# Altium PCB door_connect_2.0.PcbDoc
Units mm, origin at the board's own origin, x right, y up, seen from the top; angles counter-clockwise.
Board outline 40 x 48 mm, 2 copper layers (Top Layer, Bottom Layer); 2 components, 8 nets, 36 pads, 0 vias.
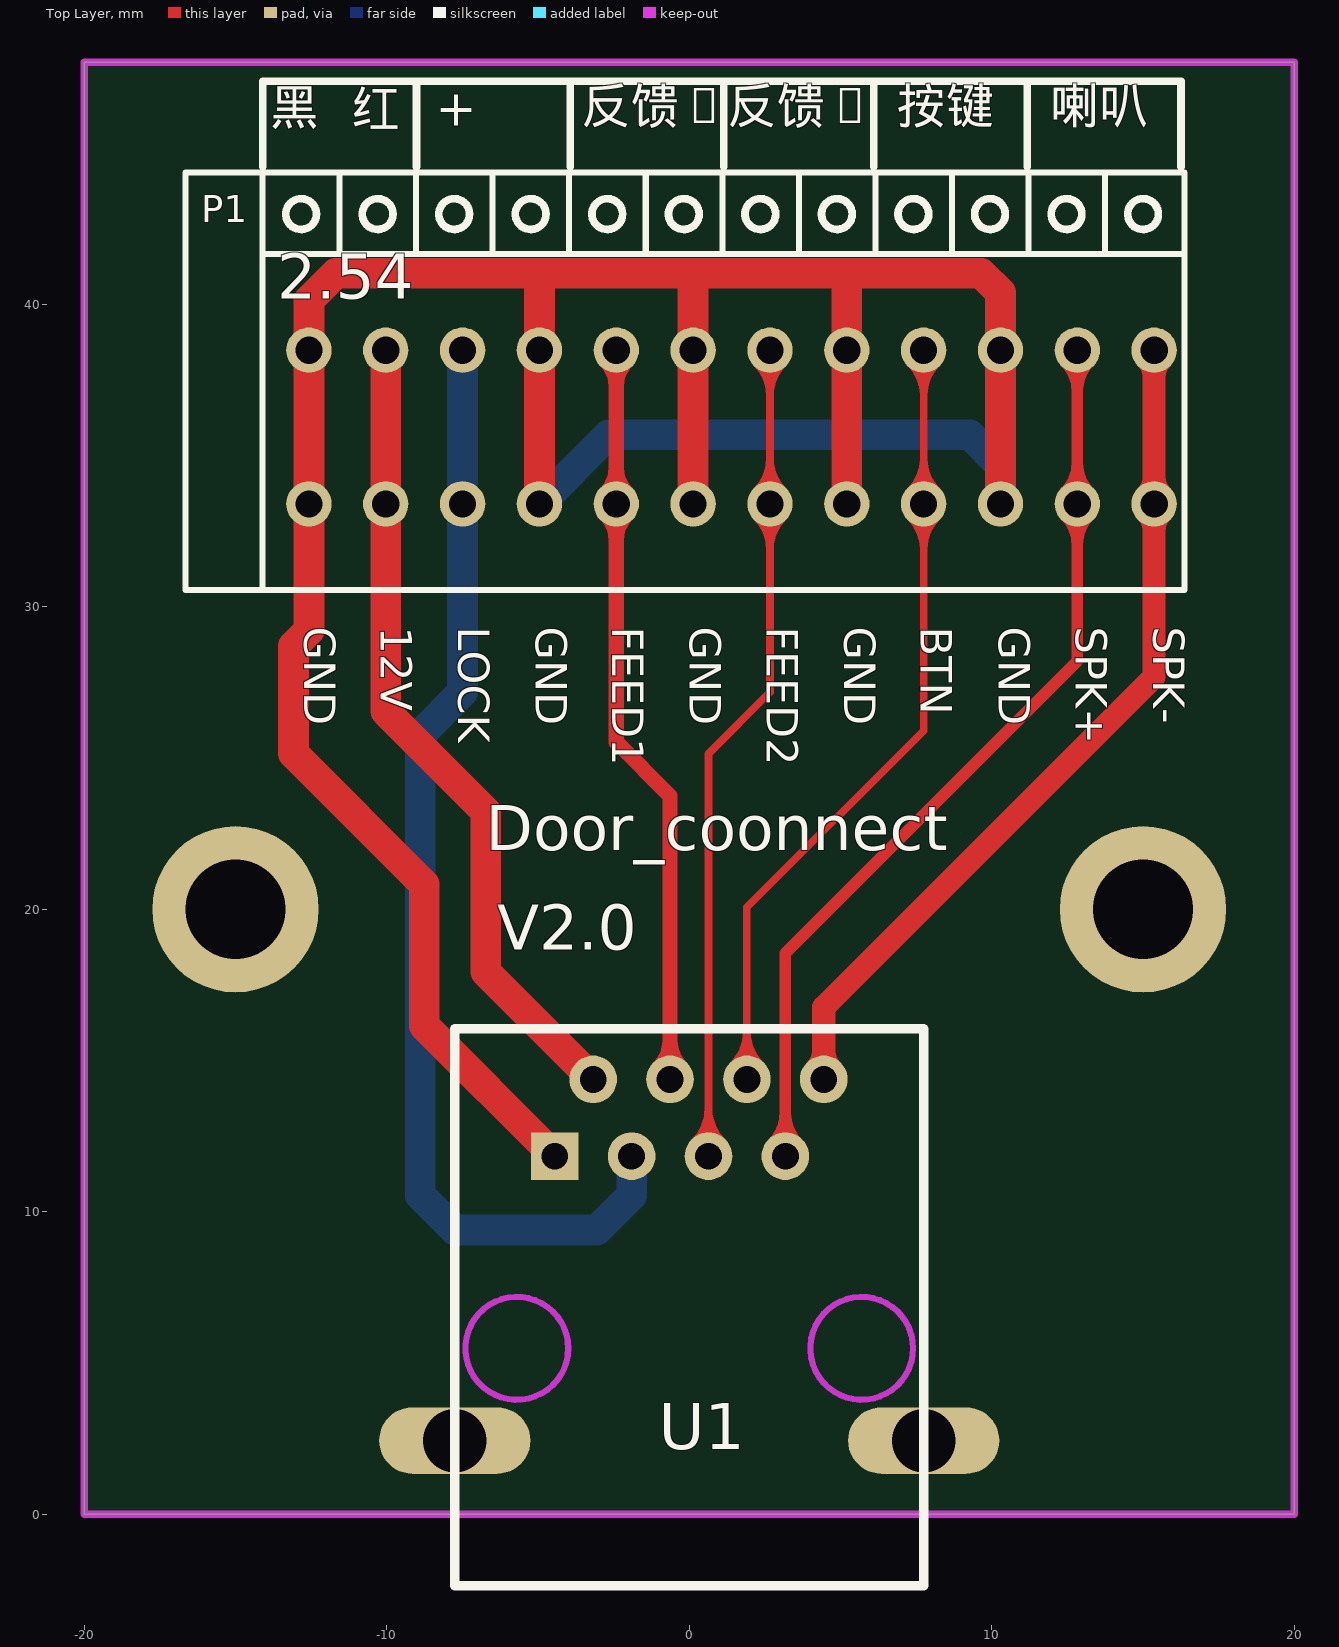
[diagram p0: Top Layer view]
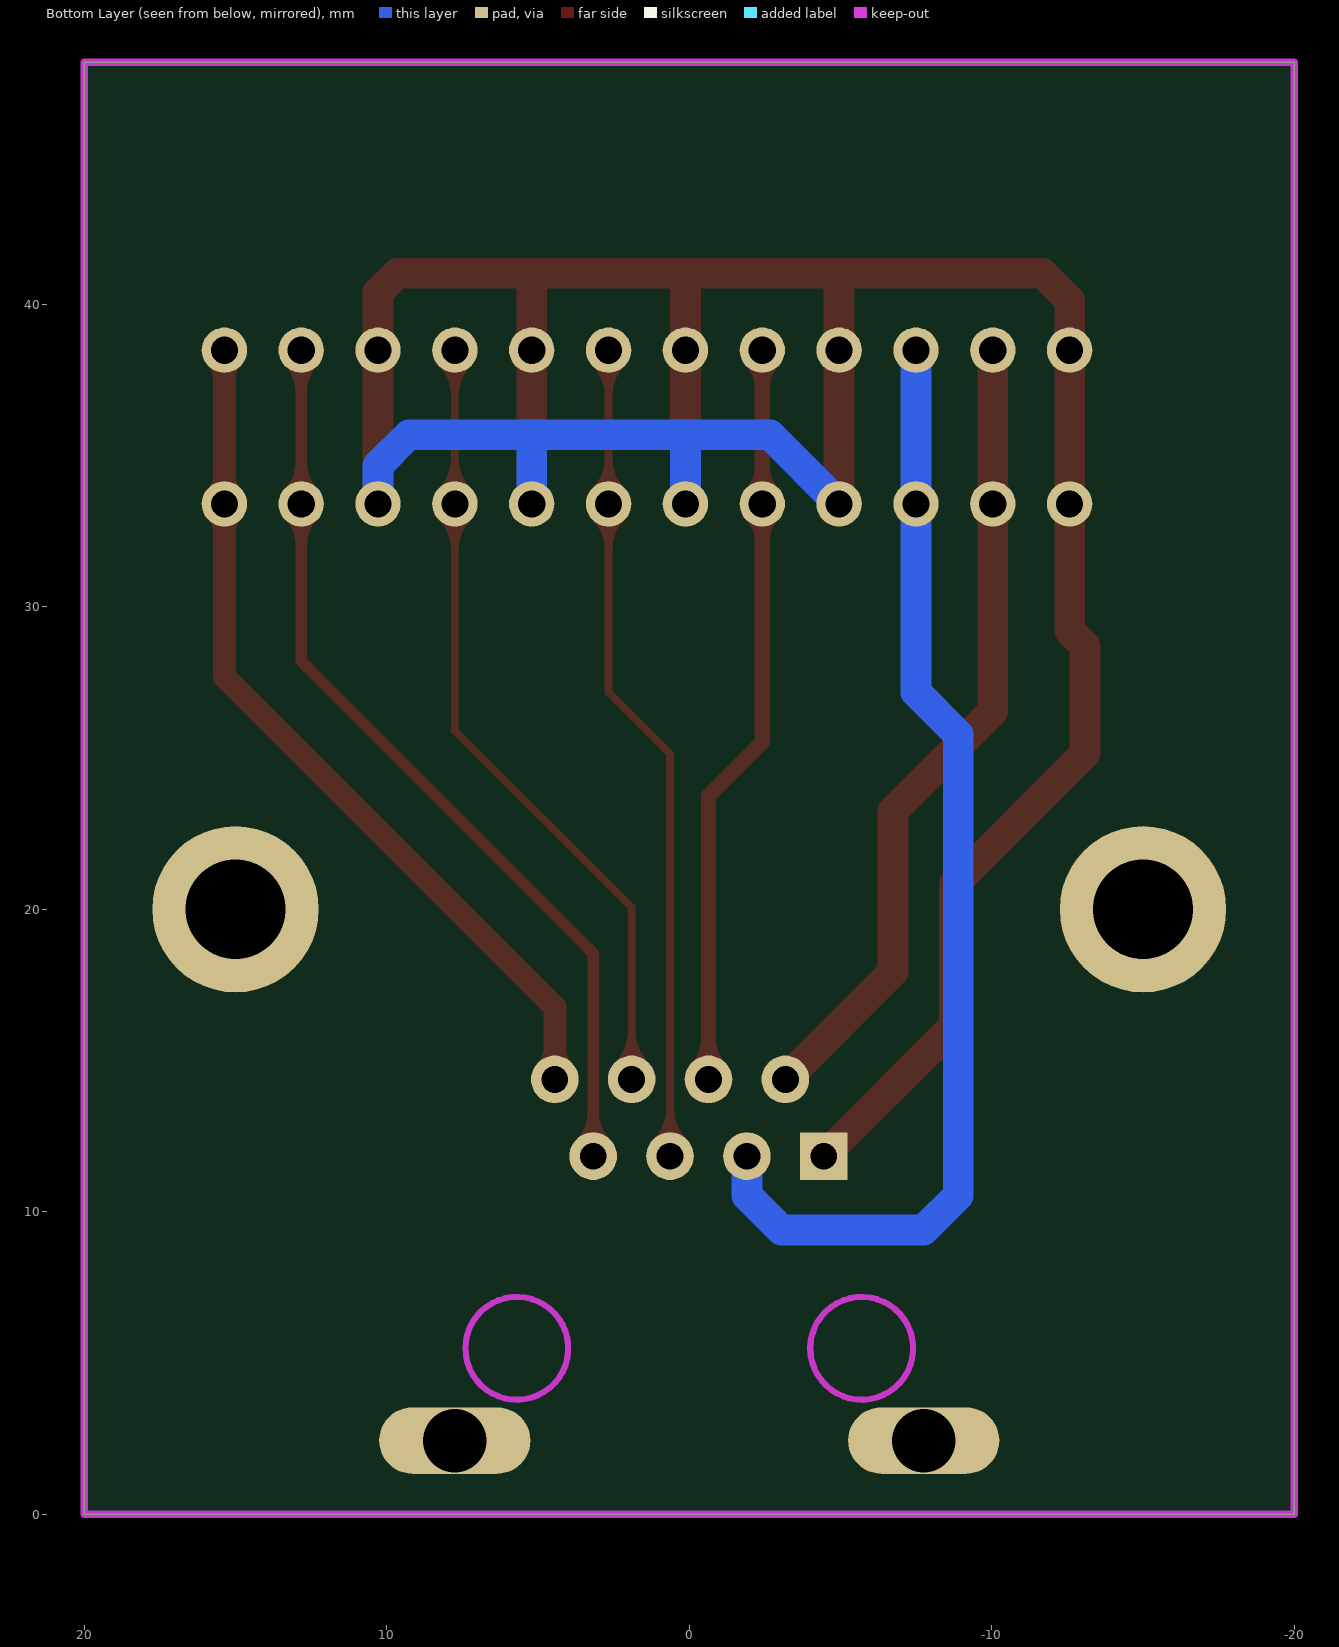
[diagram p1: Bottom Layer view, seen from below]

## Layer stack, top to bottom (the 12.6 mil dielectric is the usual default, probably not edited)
Top Layer: signal copper 0.0356
Dielectric: dielectric 0.32, FR-4, Dk 4.8
Bottom Layer: signal copper 0.0356

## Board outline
-20,0 20,0 20,48 -20,48

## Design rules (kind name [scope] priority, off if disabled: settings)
Clearance [All] p1: gap=0.178
ComponentClearance [All] p1: gap=0 collisioncheckmode=3 verticalgap=0 showdistances=FALSE
HoleSize [All] p1: absolutevalues=TRUE maxlimit=25.4 minlimit=0.025 maxpercent=80.000 minpercent=20.000
HoleToHoleClearance [All] p1: gap=0.178 allowstackedmicrovias=TRUE
MinimumSolderMaskSliver [All] p1: minsoldermaskwidth=0
PolygonConnect [All] p1: connectstyle=Relief reliefconductorwidth=0.254 reliefentries=4 polygonreliefangle="90 Angle"
RoomDefinition IO [InComponentClass('IO')] p1: confinementstyle=ConfineIn formatcopy=TRUE lockcomponents=FALSE outline -89.808,-58.012 -39.008,-58.012 -39.008,-32.612 -89.808,-32.612
RoutingVias [All] p1: holewidth=0.356 width=0.559 viastyle="Through Hole" minholewidth=0.356 minwidth=0.559 maxholewidth=7.112 maxwidth=12.7
SilkToSilkClearance [All] p1: silktosilkclearance=0
SilkscreenOverComponentPads [All] p1: minsilkscreentomaskgap=0
SolderMaskExpansion [All] p1: expansion=0.102
TestPointUsage [All] p1: valid=0 allowmultiple=FALSE
Testpoint [All] p1: side=15 testpointundercomponent=TRUE minsize=1.016 maxsize=2.54 preferedsize=1.524 minholesize=0 maxholesize=1.016 preferedholesize=0.813 testpointgrid=0.025 style=1023 order=0-112345678
Width [All] p1: maxlimit=2.54 minlimit=0.178 preferedwidth=0.178
18 further rules are at their usual default settings.

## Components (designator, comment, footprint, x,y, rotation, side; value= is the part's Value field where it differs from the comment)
P1 "Header 12" KF141R-2.54-12 -12.573,38.481 r0 top
U1 "RJ45-DTE" RJ45 0,5.488 r180 top

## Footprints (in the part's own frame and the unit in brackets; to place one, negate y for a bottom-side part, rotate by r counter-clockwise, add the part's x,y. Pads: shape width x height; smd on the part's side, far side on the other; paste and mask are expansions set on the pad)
KF141R-2.54-12 [mm]
  round 1.5 hole 0.9: 1(0,-5.08) 1(0,0) 2(2.54,-5.08) 2(2.54,0) 3(5.08,-5.08) 3(5.08,0) 4(7.62,-5.08) 4(7.62,0) 5(10.16,-5.08) 5(10.16,0) 6(12.7,-5.08) 6(12.7,0) 7(15.24,-5.08) 7(15.24,0) 8(17.78,-5.08) 8(17.78,0) 9(20.32,-5.08) 9(20.32,0) 10(22.86,-5.08) 10(22.86,0) 11(25.4,-5.08) 11(25.4,0) 12(27.94,-5.08) 12(27.94,0)
  silkscreen extent -4.08,-7.93 28.94,5.87
RJ45 [mil]
  oval 196.85x86.61 hole 82.68: 0(-305.12,120.08) 0(305.12,120.08)
  rect 62x62 hole 35: 1(175,-250)
  round 62 hole 35: 2(125,-350) 3(75,-250) 4(25,-350) 5(-25,-250) 6(-75,-350) 7(-125,-250) 8(-175,-350)
  Keep-Out Layer circle w8: c224.41,0 r66.93
  Keep-Out Layer circle w8: c-224.41,0 r66.93
  silkscreen extent -305,-416 305,309

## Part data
P1: "Header, 12-Pin"

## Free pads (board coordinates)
  round 5.5 hole 3.3: 0(-15,20) 0(15,20)

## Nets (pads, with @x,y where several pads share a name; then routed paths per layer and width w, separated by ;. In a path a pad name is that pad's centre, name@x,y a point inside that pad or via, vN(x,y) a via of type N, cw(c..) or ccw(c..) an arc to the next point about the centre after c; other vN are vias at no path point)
BTN: P1.9 U1.6 | length 41.9
  Top Layer w0.254: U1.6@1.438,14.845 ccw(c0.311,15.972) 1.905,15.972 ccw(c3.499,15.972) U1.6@2.372,14.845 ; U1.6@1.618,14.665 ccw(c0.924,15.359) 1.905,15.359 ccw(c2.886,15.359) U1.6@2.192,14.665 ; U1.6 1.905,20.066 7.747,25.908 7.747,33.401 P1.9@7.747,38.481 ; P1.9@7.306,32.96 cw(c6.243,31.897) 7.747,31.897 cw(c9.251,31.897) P1.9@8.188,32.96 ; P1.9@7.306,33.842 ccw(c6.243,34.905) 7.747,34.905 ccw(c9.251,34.905) P1.9@8.188,33.842 ; P1.9@7.306,38.04 cw(c6.243,36.977) 7.747,36.977 cw(c9.251,36.977) P1.9@8.188,38.04 ; P1.9@7.486,33.14 cw(c6.856,32.51) 7.747,32.51 cw(c8.638,32.51) P1.9@8.008,33.14 ; P1.9@7.486,33.662 ccw(c6.856,34.292) 7.747,34.292 ccw(c8.638,34.292) P1.9@8.008,33.662 ; P1.9@7.486,38.22 cw(c6.856,37.59) 7.747,37.59 cw(c8.638,37.59) P1.9@8.008,38.22
D12V: P1.2 U1.2 | length 26.9
  Top Layer w1.016: P1.2@-10.033,38.481 -10.033,33.401 -10.033,26.543 -6.731,23.241 -6.731,17.934 U1.2
FEED1: P1.5 U1.4 | length 32.5
  Top Layer w0.508: P1.5@-2.764,33.05 cw(c-3.61,32.204) -2.413,32.204 cw(c-1.216,32.204) P1.5@-2.062,33.05 ; P1.5@-2.764,33.752 ccw(c-3.61,34.598) -2.413,34.598 ccw(c-1.216,34.598) P1.5@-2.062,33.752 ; P1.5@-2.764,38.13 cw(c-3.61,37.284) -2.413,37.284 cw(c-1.216,37.284) P1.5@-2.062,38.13 ; P1.5@-2.413,38.481 -2.413,33.401 -2.413,25.527 -0.635,23.749 U1.4 ; U1.4@-1.012,14.755 ccw(c-1.923,15.666) -0.635,15.666 ccw(c0.653,15.666) U1.4@-0.258,14.755
FEED2: P1.7 U1.5 | length 42.8
  Top Layer w0.254: U1.5@0.168,12.305 ccw(c-0.959,13.432) 0.635,13.432 ccw(c2.229,13.432) U1.5@1.102,12.305 ; U1.5@0.348,12.125 ccw(c-0.346,12.819) 0.635,12.819 ccw(c1.616,12.819) U1.5@0.922,12.125 ; U1.5 0.635,25.146 2.667,27.178 2.667,33.401 P1.7@2.667,38.481 ; P1.7@2.226,32.96 cw(c1.163,31.897) 2.667,31.897 cw(c4.171,31.897) P1.7@3.108,32.96 ; P1.7@2.226,33.842 ccw(c1.163,34.905) 2.667,34.905 ccw(c4.171,34.905) P1.7@3.108,33.842 ; P1.7@2.226,38.04 cw(c1.163,36.977) 2.667,36.977 cw(c4.171,36.977) P1.7@3.108,38.04 ; P1.7@2.406,33.14 cw(c1.776,32.51) 2.667,32.51 cw(c3.558,32.51) P1.7@2.928,33.14 ; P1.7@2.406,33.662 ccw(c1.776,34.292) 2.667,34.292 ccw(c3.558,34.292) P1.7@2.928,33.662 ; P1.7@2.406,38.22 cw(c1.776,37.59) 2.667,37.59 cw(c3.558,37.59) P1.7@2.928,38.22
GND: P1.1 P1.4 P1.6 P1.8 P1.10 U1.1 | length 106.7
  Top Layer w1.016: P1.4@-4.953,33.401 -4.953,38.481 -4.953,40.64 ; U1.1 -8.763,16.156 -8.763,20.828 -13.081,25.146 -13.081,28.702 -12.573,29.21 -12.573,33.401 -12.573,38.481 -12.573,40.132 -11.684,41.021 9.652,41.021 10.287,40.386 10.287,38.481 P1.10@10.287,33.401 ; P1.6@0.127,33.401 0.127,38.481 0.127,40.894 ; P1.8@5.207,33.401 5.207,38.481 5.207,40.894
  Bottom Layer w1.016: P1.4@-4.953,33.401 -2.667,35.687 9.271,35.687 10.287,34.671 P1.10@10.287,33.401 ; P1.6@0.127,33.401 0.127,35.56 ; P1.8@5.207,33.401 5.207,35.306
LOCK_V+: P1.3 U1.3 | length 37.7
  Bottom Layer w1.016: P1.3@-7.493,38.481 -7.493,33.401 -7.493,27.178 -8.89,25.781 -8.89,10.541 -7.747,9.398 -3.048,9.398 -1.905,10.541 U1.3
SPEAKERA: P1.11 U1.7 | length 39.3
  Top Layer w0.381: U1.7@2.753,12.26 ccw(c1.734,13.279) 3.175,13.279 ccw(c4.616,13.279) U1.7@3.597,12.26 ; U1.7 3.175,18.542 12.827,28.194 12.827,33.401 P1.11@12.827,38.481 ; P1.11@12.431,33.005 cw(c11.476,32.05) 12.827,32.05 cw(c14.178,32.05) P1.11@13.223,33.005 ; P1.11@12.431,33.797 ccw(c11.476,34.752) 12.827,34.752 ccw(c14.178,34.752) P1.11@13.223,33.797 ; P1.11@12.431,38.085 cw(c11.476,37.13) 12.827,37.13 cw(c14.178,37.13) P1.11@13.223,38.085
SPEAKERB: P1.12 U1.8 | length 34.4
  Top Layer w0.762: U1.8@4.158,14.665 ccw(c3.464,15.359) 4.445,15.359 ccw(c5.426,15.359) U1.8@4.732,14.665 ; U1.8 4.445,16.764 15.367,27.686 15.367,33.401 P1.12@15.367,38.481 ; P1.12@15.106,33.14 cw(c14.476,32.51) 15.367,32.51 cw(c16.258,32.51) P1.12@15.628,33.14 ; P1.12@15.106,33.662 ccw(c14.476,34.292) 15.367,34.292 ccw(c16.258,34.292) P1.12@15.628,33.662 ; P1.12@15.106,38.22 cw(c14.476,37.59) 15.367,37.59 cw(c16.258,37.59) P1.12@15.628,38.22
pads on no net: U1.0

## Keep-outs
Keep-Out Layer:
  the board outline again, w0.254

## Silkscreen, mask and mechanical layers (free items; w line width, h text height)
Top Overlay:
  lines w0.254: -14.097,44.54 -14.097,47.371 -9.017,47.371 ; -9.017,44.54 -9.017,47.371 ; -3.937,44.54 -3.937,47.371 ; 1.143,44.54 1.143,47.371 ; 6.096,44.54 6.096,47.371 ; 11.176,44.54 11.176,47.371 ; 16.256,44.54 16.256,47.371 11.176,47.371 ; -9.017,47.371 -3.937,47.371 ; -3.937,47.371 1.143,47.371 ; 1.143,47.371 6.096,47.371 ; 6.096,47.371 11.176,47.371
  text "按键" at 6.858,45.593 h2.03
  text "反馈1" at -3.556,45.579 h2.03
  text "反馈2" at 1.27,45.579 h2.03
  text "喇叭" at 11.938,45.579 h2.03
  text "黑" at -13.843,45.543 h2.03
  text "+" at -8.382,45.506 h2.03
  text "红" at -11.176,45.48 h2.03
  text "GND" at -13.081,29.337 h1.78 r270
  text "12V" at -10.549,29.337 h1.78 r270
  text "LOCK" at -7.978,29.337 h1.78 r270
  text "GND" at -5.426,29.337 h1.78 r270
  text "FEED1" at -2.894,29.337 h1.78 r270
  text "GND" at -0.323,29.337 h1.78 r270
  text "FEED2" at 2.209,29.337 h1.78 r270
  text "GND" at 4.78,29.337 h1.78 r270
  text "BTN" at 7.312,29.337 h1.78 r270
  text "GND" at 9.883,29.337 h1.78 r270
  text "SPK+" at 12.434,29.337 h1.78 r270
  text "SPK-" at 14.986,29.337 h1.78 r270
  text "Door_coonnect" at -6.731,21.463 h2.54
  text "V2.0" at -6.35,18.161 h2.54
